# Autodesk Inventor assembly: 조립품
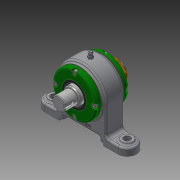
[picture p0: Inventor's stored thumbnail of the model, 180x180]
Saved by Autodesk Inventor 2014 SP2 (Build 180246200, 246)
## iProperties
Created: 2019-05
Part Number: 조립품
Document SubType Name: Assembly
Designer: gs
Author: gs
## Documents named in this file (13)
- C:\Users\gs\Desktop\490504v1031\조립품.iam
- C:\Users\gs\Desktop\490504v1031\본체.ipt
- C:\Users\gs\Desktop\490504v1031\커버.ipt
- C:\Users\gs\Desktop\490504v1031\오일 실 28 40 5 B.ipt
- C:\Users\gs\Desktop\490504v1031\개스킷.ipt
- C:\Users\gs\Desktop\490504v1031\앵귤러 볼 베어링 7205.ipt
- C:\Users\gs\Desktop\490504v1031\칼라.ipt
- C:\Users\gs\Desktop\490504v1031\축.ipt
- C:\Users\gs\Desktop\490504v1031\베어링너트.ipt
- C:\Users\gs\Desktop\490504v1031\볼트 M4.ipt
- C:\Users\gs\Desktop\490504v1031\그리스니플개스킷.ipt
- C:\Users\gs\Desktop\490504v1031\그리스니플 M6.ipt
- 그리스니플  M6.ipt
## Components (4 placed, 3 different names)
1. 개스킷:1
2. 개스킷:2
3. 그리스니플개스킷:1
4. 그리스니플  M6:1 — 각도:2
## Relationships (1: Angle 1)
- 각도:2 [Angle]: 그리스니플  M6:1
